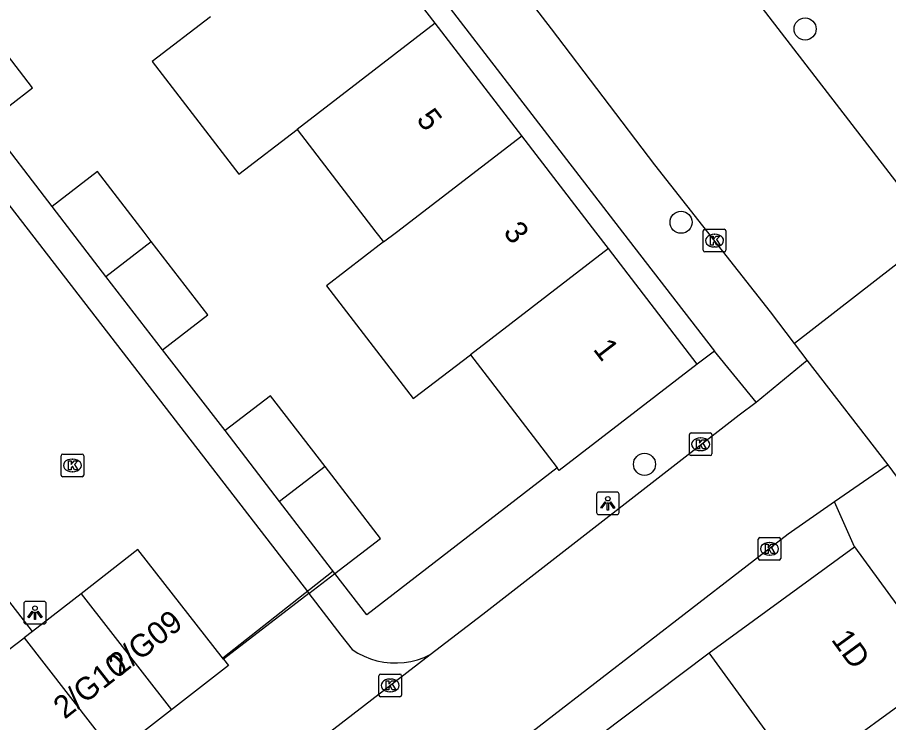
# Model space of a CAD drawing. Extents: x 159222 to 160346, y 381249 to 382166.
# Drawn here: x 159730.02 to 159768.58, y 381478.29 to 381509.5 of the extents above; entities that cross this region are included whole.
import ezdxf

# ---------------------------------------------------------------- set-up
doc = ezdxf.new("R2010")
doc.units = 0
for name, color, linetype in [('IMGEO_Boom', 7, 'Continuous'), ('IMGEO_Hek', 7, 'Continuous'), ('IMGEO_Kolk', 7, 'Continuous'), ('IMGEO_Lichtpunt', 7, 'Continuous'), ('IMGEO_Muur', 7, 'Continuous'), ('IMGEO_Pand', 7, 'Continuous'), ('IMGEO_Pand_nummerreeks', 7, 'Continuous'), ('IMGEO_Rijbaan_lokaal_gesloten', 7, 'Continuous'), ('IMGEO_Rijbaan_lokaal_open', 7, 'Continuous'), ('IMGEO_Voetpad_open', 7, 'Continuous')]:
    doc.layers.add(name, color=color, linetype=linetype)

msp = doc.modelspace()

# ---------------------------------------------------------------- linework, layer by layer
at = {"layer": 'IMGEO_Boom'}
for centre in [(159764.885, 381508.987), (159759.393, 381500.434), (159757.775, 381489.722)]:
    msp.add_circle(centre, 0.489, dxfattribs=at)
at = {"layer": 'IMGEO_Hek'}
msp.add_lwpolyline([(159744.002, 381484.991), (159739.107, 381481.143)], dxfattribs=at)
at = {"layer": 'IMGEO_Kolk'}
for p, q in [((159760.375, 381499.196), (159760.375, 381500.048)), ((159760.45, 381500.122), (159761.302, 381500.122)), ((159760.863, 381499.902), (159760.888, 381499.902)), ((159761.376, 381500.048), (159761.376, 381499.196)), ((159761.302, 381499.122), (159760.45, 381499.122)), ((159760.886, 381499.342), (159760.861, 381499.342)), ((159759.76, 381490.181), (159759.76, 381491.033)), ((159759.835, 381491.107), (159760.687, 381491.107)), ((159760.761, 381491.033), (159760.761, 381490.181)), ((159760.248, 381490.887), (159760.273, 381490.887)), ((159732.032, 381490.17), (159732.884, 381490.17)), ((159760.271, 381490.327), (159760.246, 381490.327)), ((159731.957, 381489.244), (159731.957, 381490.096)), ((159732.445, 381489.95), (159732.47, 381489.95)), ((159732.958, 381490.096), (159732.958, 381489.244)), ((159760.687, 381490.107), (159759.835, 381490.107)), ((159732.468, 381489.39), (159732.443, 381489.39)), ((159732.884, 381489.17), (159732.032, 381489.17)), ((159762.805, 381485.554), (159762.805, 381486.406)), ((159762.88, 381486.48), (159763.732, 381486.48)), ((159763.806, 381486.406), (159763.806, 381485.554)), ((159763.293, 381486.26), (159763.318, 381486.26)), ((159763.316, 381485.7), (159763.291, 381485.7)), ((159763.732, 381485.48), (159762.88, 381485.48)), ((159746.02, 381479.51), (159746.02, 381480.362)), ((159746.095, 381480.436), (159746.947, 381480.436)), ((159746.508, 381480.216), (159746.533, 381480.216)), ((159747.021, 381480.362), (159747.021, 381479.51)), ((159746.947, 381479.436), (159746.095, 381479.436)), ((159746.531, 381479.656), (159746.506, 381479.656))]:
    msp.add_line(p, q, dxfattribs=at)
for points in [[(159760.375, 381499.196), (159760.375, 381500.048)], [(159760.45, 381500.122), (159761.302, 381500.122)], [(159760.696, 381499.822), (159760.819, 381499.822), (159760.819, 381499.671), (159760.949, 381499.822), (159761.113, 381499.822), (159760.967, 381499.671), (159761.12, 381499.422), (159760.968, 381499.422), (159760.883, 381499.586), (159760.819, 381499.519), (159760.819, 381499.422), (159760.696, 381499.422), (159760.696, 381499.822)], [(159761.376, 381500.048), (159761.376, 381499.196)], [(159761.302, 381499.122), (159760.45, 381499.122)], [(159759.76, 381490.181), (159759.76, 381491.033)], [(159759.835, 381491.107), (159760.687, 381491.107)], [(159760.761, 381491.033), (159760.761, 381490.181)], [(159760.081, 381490.807), (159760.204, 381490.807), (159760.204, 381490.656), (159760.334, 381490.807), (159760.498, 381490.807), (159760.352, 381490.656), (159760.505, 381490.407), (159760.353, 381490.407), (159760.268, 381490.571), (159760.204, 381490.504), (159760.204, 381490.407), (159760.081, 381490.407), (159760.081, 381490.807)], [(159732.032, 381490.17), (159732.884, 381490.17)], [(159731.957, 381489.244), (159731.957, 381490.096)], [(159732.278, 381489.87), (159732.401, 381489.87), (159732.401, 381489.719), (159732.531, 381489.87), (159732.695, 381489.87), (159732.549, 381489.719), (159732.702, 381489.47), (159732.55, 381489.47), (159732.465, 381489.634), (159732.401, 381489.567), (159732.401, 381489.47), (159732.278, 381489.47), (159732.278, 381489.87)], [(159732.958, 381490.096), (159732.958, 381489.244)], [(159760.687, 381490.107), (159759.835, 381490.107)], [(159732.884, 381489.17), (159732.032, 381489.17)], [(159762.805, 381485.554), (159762.805, 381486.406)], [(159762.88, 381486.48), (159763.732, 381486.48)], [(159763.806, 381486.406), (159763.806, 381485.554)], [(159763.126, 381486.18), (159763.249, 381486.18), (159763.249, 381486.029), (159763.379, 381486.18), (159763.543, 381486.18), (159763.397, 381486.029), (159763.55, 381485.78), (159763.398, 381485.78), (159763.313, 381485.944), (159763.249, 381485.877), (159763.249, 381485.78), (159763.126, 381485.78), (159763.126, 381486.18)], [(159763.732, 381485.48), (159762.88, 381485.48)], [(159746.02, 381479.51), (159746.02, 381480.362)], [(159746.095, 381480.436), (159746.947, 381480.436)], [(159746.341, 381480.136), (159746.464, 381480.136), (159746.464, 381479.985), (159746.594, 381480.136), (159746.758, 381480.136), (159746.612, 381479.985), (159746.765, 381479.736), (159746.613, 381479.736), (159746.528, 381479.9), (159746.464, 381479.833), (159746.464, 381479.736), (159746.341, 381479.736), (159746.341, 381480.136)], [(159747.021, 381480.362), (159747.021, 381479.51)], [(159746.947, 381479.436), (159746.095, 381479.436)]]:
    msp.add_lwpolyline(points, dxfattribs=at)
for centre, start, end in [((159760.452, 381500.046), 91.552, 178.448), ((159760.452, 381500.046), 91.552, 178.448), ((159761.3, 381500.046), 1.552, 88.448), ((159761.3, 381500.046), 1.552, 88.448), ((159760.452, 381499.198), 181.552, 268.448), ((159760.452, 381499.198), 181.552, 268.448), ((159761.3, 381499.198), 271.552, 358.448), ((159761.3, 381499.198), 271.552, 358.448), ((159759.837, 381491.031), 91.552, 178.448), ((159759.837, 381491.031), 91.552, 178.448), ((159760.685, 381491.031), 1.552, 88.448), ((159760.685, 381491.031), 1.552, 88.448), ((159732.034, 381490.094), 91.552, 178.448), ((159732.034, 381490.094), 91.552, 178.448), ((159732.882, 381490.094), 1.552, 88.448), ((159732.882, 381490.094), 1.552, 88.448), ((159759.837, 381490.183), 181.552, 268.448), ((159759.837, 381490.183), 181.552, 268.448), ((159760.685, 381490.183), 271.552, 358.448), ((159760.685, 381490.183), 271.552, 358.448), ((159732.034, 381489.246), 181.552, 268.448), ((159732.034, 381489.246), 181.552, 268.448), ((159732.882, 381489.246), 271.552, 358.448), ((159732.882, 381489.246), 271.552, 358.448), ((159762.882, 381486.404), 91.552, 178.448), ((159762.882, 381486.404), 91.552, 178.448), ((159763.73, 381486.404), 1.552, 88.448), ((159763.73, 381486.404), 1.552, 88.448), ((159762.882, 381485.556), 181.552, 268.448), ((159762.882, 381485.556), 181.552, 268.448), ((159763.73, 381485.556), 271.552, 358.448), ((159763.73, 381485.556), 271.552, 358.448), ((159746.097, 381480.36), 91.552, 178.448), ((159746.097, 381480.36), 91.552, 178.448), ((159746.945, 381480.36), 1.552, 88.448), ((159746.945, 381480.36), 1.552, 88.448), ((159746.097, 381479.512), 181.552, 268.448), ((159746.097, 381479.512), 181.552, 268.448), ((159746.945, 381479.512), 271.552, 358.448), ((159746.945, 381479.512), 271.552, 358.448)]:
    msp.add_arc(centre, 0.0765, start, end, dxfattribs=at)
for centre, major_axis, ratio, start_param, end_param in [((159760.862, 381499.622), (-0.387, 0.002), 0.722429, 4.712389, 7.853982), ((159760.887, 381499.622), (-0.39, 0.002), 0.717154, 1.570796, 4.712389), ((159760.247, 381490.607), (-0.387, 0.002), 0.722429, 4.712389, 7.853982), ((159760.272, 381490.607), (-0.39, 0.002), 0.717154, 1.570796, 4.712389), ((159732.444, 381489.67), (-0.387, 0.002), 0.722429, 4.712389, 7.853982), ((159732.469, 381489.67), (-0.39, 0.002), 0.717154, 1.570796, 4.712389), ((159763.292, 381485.98), (-0.387, 0.002), 0.722429, 4.712389, 7.853982), ((159763.317, 381485.98), (-0.39, 0.002), 0.717154, 1.570796, 4.712389), ((159746.507, 381479.936), (-0.387, 0.002), 0.722429, 4.712389, 7.853982), ((159746.532, 381479.936), (-0.39, 0.002), 0.717154, 1.570796, 4.712389)]:
    msp.add_ellipse(centre, major_axis=major_axis, ratio=ratio, start_param=start_param, end_param=end_param, dxfattribs=at)
at = {"layer": 'IMGEO_Lichtpunt'}
for p, q in [((159755.653, 381488.399), (159755.653, 381487.592)), ((159755.653, 381488.399), (159755.653, 381487.592)), ((159756.555, 381488.494), (159755.747, 381488.494)), ((159756.555, 381488.494), (159755.747, 381488.494)), ((159756.649, 381487.592), (159756.649, 381488.399)), ((159756.649, 381487.592), (159756.649, 381488.399)), ((159755.747, 381487.498), (159756.555, 381487.498)), ((159755.747, 381487.498), (159756.555, 381487.498)), ((159731.204, 381483.653), (159730.396, 381483.653)), ((159731.204, 381483.653), (159730.396, 381483.653)), ((159730.302, 381483.558), (159730.302, 381482.751)), ((159730.302, 381483.558), (159730.302, 381482.751)), ((159731.298, 381482.751), (159731.298, 381483.558)), ((159731.298, 381482.751), (159731.298, 381483.558)), ((159730.396, 381482.657), (159731.204, 381482.657)), ((159730.396, 381482.657), (159731.204, 381482.657))]:
    msp.add_line(p, q, dxfattribs=at)
for points in [[(159756.027, 381488.063), (159756.066, 381488.035), (159755.878, 381487.773), (159755.84, 381487.8), (159756.027, 381488.063)], [(159756.129, 381488.015), (159756.176, 381488.015), (159756.176, 381487.693), (159756.129, 381487.693), (159756.129, 381488.015)], [(159756.239, 381488.035), (159756.277, 381488.062), (159756.464, 381487.8), (159756.425, 381487.772), (159756.239, 381488.035)], [(159730.676, 381483.222), (159730.715, 381483.194), (159730.527, 381482.932), (159730.489, 381482.959), (159730.676, 381483.222)], [(159730.888, 381483.194), (159730.926, 381483.221), (159731.113, 381482.959), (159731.074, 381482.931), (159730.888, 381483.194)], [(159730.778, 381483.174), (159730.825, 381483.174), (159730.825, 381482.852), (159730.778, 381482.852), (159730.778, 381483.174)]]:
    msp.add_lwpolyline(points, dxfattribs=at)
for centre in [(159756.152, 381488.197), (159730.801, 381483.356)]:
    msp.add_circle(centre, 0.0994, dxfattribs=at)
for centre, start, end in [((159755.747, 381488.399), 90, 180), ((159755.747, 381488.399), 90, 180), ((159756.555, 381488.399), 0, 90), ((159756.555, 381488.399), 0, 90), ((159755.747, 381487.592), 180, 270), ((159755.747, 381487.592), 180, 270), ((159756.555, 381487.592), 270, 0), ((159756.555, 381487.592), 270, 360), ((159730.396, 381483.558), 90, 180), ((159730.396, 381483.558), 90, 180), ((159731.204, 381483.558), 0, 90), ((159731.204, 381483.558), 0, 90), ((159730.396, 381482.751), 180, 270), ((159730.396, 381482.751), 180, 270), ((159731.204, 381482.751), 270, 0), ((159731.204, 381482.751), 270, 360)]:
    msp.add_arc(centre, 0.0946, start, end, dxfattribs=at)
at = {"layer": 'IMGEO_Muur'}
msp.add_lwpolyline([(159753.414, 381475.928), (159760.63, 381481.373)], dxfattribs=at)
at = {"layer": 'IMGEO_Pand'}
for points in [[(159748.509, 381509.241), (159744.679, 381514.222)], [(159728.702, 381504.843), (159730.692, 381506.375), (159728.265, 381509.527)], [(159738.565, 381509.52), (159735.992, 381507.541), (159739.823, 381502.561), (159742.397, 381504.541)], [(159748.509, 381509.241), (159742.397, 381504.541)], [(159752.34, 381504.259), (159748.509, 381509.241)], [(159742.397, 381504.541), (159745.892, 381500), (159746.23, 381499.561)], [(159746.23, 381499.561), (159746.801, 381500), (159752.34, 381504.259)], [(159756.177, 381499.27), (159755.615, 381500), (159752.34, 381504.259)], [(159735.948, 381499.582), (159735.627, 381500), (159733.566, 381502.68), (159731.558, 381501.133)], [(159733.938, 381498.036), (159732.429, 381500), (159731.558, 381501.133)], [(159733.938, 381498.036), (159735.948, 381499.582)], [(159736.436, 381494.787), (159738.447, 381496.332), (159735.948, 381499.582)], [(159746.23, 381499.561), (159743.704, 381497.617), (159747.543, 381492.629), (159750.069, 381494.573)], [(159756.177, 381499.27), (159750.069, 381494.573)], [(159760.111, 381494.153), (159756.177, 381499.27)], [(159736.436, 381494.787), (159733.938, 381498.036)], [(159750.069, 381494.573), (159750.959, 381493.417), (159753.916, 381489.567)], [(159760.111, 381494.153), (159754.005, 381489.451), (159753.916, 381489.567)], [(159743.635, 381489.625), (159741.23, 381492.756), (159739.222, 381491.214)], [(159741.628, 381488.082), (159739.222, 381491.214)], [(159743.635, 381489.625), (159741.628, 381488.082)], [(159744.077, 381484.893), (159746.085, 381486.436), (159743.635, 381489.625)], [(159744.077, 381484.893), (159741.628, 381488.082)], [(159739.14, 381481.1), (159735.356, 381485.955), (159732.837, 381483.992)], [(159760.63, 381481.373), (159767.07, 381486.073)], [(159767.07, 381486.073), (159771.094, 381480.559)], [(159730.695, 381482.323), (159728.774, 381484.792)], [(159732.837, 381483.992), (159730.695, 381482.323)], [(159732.837, 381483.992), (159736.844, 381478.851)], [(159730.695, 381482.323), (159730.314, 381482.035)], [(159727.764, 381480.113), (159730.314, 381482.035)], [(159730.314, 381482.035), (159734.325, 381476.888)], [(159764.65, 381475.863), (159760.63, 381481.373)], [(159739.14, 381481.1), (159739.363, 381480.814), (159736.844, 381478.851)], [(159764.65, 381475.863), (159771.094, 381480.559)], [(159736.844, 381478.851), (159734.325, 381476.888)]]:
    msp.add_lwpolyline(points, dxfattribs=at)
at = {"layer": 'IMGEO_Rijbaan_lokaal_gesloten'}
for points in [[(159764.419, 381495.062), (159763.358, 381496.462), (159758.238, 381502.981), (159753.664, 381509), (159740.852, 381525.618), (159730.632, 381538.903)], [(159761.639, 381511.66), (159770.073, 381500.702), (159770.613, 381500), (159770.669, 381499.927)], [(159770.669, 381499.927), (159764.419, 381495.062)]]:
    msp.add_lwpolyline(points, dxfattribs=at)
at = {"layer": 'IMGEO_Rijbaan_lokaal_open'}
for points in [[(159764.981, 381494.334), (159764.419, 381495.062)], [(159762.721, 381492.467), (159764.981, 381494.334)], [(159768.565, 381489.696), (159764.981, 381494.334)], [(159748.29, 381481.298), (159750.62, 381483.094), (159761.958, 381491.907), (159762.721, 381492.467)], [(159768.565, 381489.696), (159766.186, 381488.065)], [(159773.167, 381483.677), (159769.23, 381488.8), (159768.565, 381489.696)], [(159766.186, 381488.065), (159764.131, 381486.626), (159751.301, 381476.717), (159744.553, 381471.43), (159742.623, 381469.918), (159739.562, 381467.58), (159734.756, 381463.908), (159734.716, 381463.878), (159732.148, 381461.916), (159729.658, 381459.972), (159727.311, 381458.139), (159725.019, 381456.349), (159718.247, 381451.061), (159710.157, 381444.811), (159708.054, 381443.186), (159705.454, 381441.178), (159700.32, 381437.219), (159693.644, 381432.07), (159691.194, 381430.18), (159689.16, 381428.611), (159683.372, 381424.074), (159680.529, 381421.765)], [(159742.92, 381484.004), (159739.14, 381481.1)], [(159742.92, 381484.004), (159744.342, 381482.166), (159744.836, 381481.526), (159745.093, 381481.366), (159745.364, 381481.229), (159745.646, 381481.117), (159745.936, 381481.031), (159746.234, 381480.971), (159746.535, 381480.938), (159746.838, 381480.932), (159747.141, 381480.953), (159747.44, 381481.001), (159747.734, 381481.075), (159748.02, 381481.175), (159748.29, 381481.298)], [(159697.98, 381442.46), (159701.918, 381445.502), (159718.274, 381458.259), (159737.837, 381473.24), (159748.29, 381481.298)]]:
    msp.add_lwpolyline(points, dxfattribs=at)
at = {"layer": 'IMGEO_Voetpad_open'}
for points in [[(159729.233, 381534.307), (159729.955, 381534.85), (159756.805, 381500), (159760.87, 381494.724)], [(159715.326, 381502.074), (159723.871, 381508.651), (159742.854, 381484.089), (159742.92, 381484.004)], [(159731.558, 381501.133), (159728.702, 381504.843)], [(159739.222, 381491.214), (159736.436, 381494.787)], [(159760.87, 381494.724), (159760.111, 381494.153)], [(159762.721, 381492.467), (159760.87, 381494.724)], [(159753.916, 381489.567), (159745.49, 381483.053), (159744.077, 381484.893)], [(159767.07, 381486.073), (159766.186, 381488.065)], [(159742.92, 381484.004), (159744.077, 381484.893)], [(159753.414, 381475.928), (159760.63, 381481.373)]]:
    msp.add_lwpolyline(points, dxfattribs=at)

# ---------------------------------------------------------------- texts
at = {"layer": 'IMGEO_Pand_nummerreeks'}
for s, rotation, p in [('5', 307.5602, (159747.646, 381504.981)), ('3', 307.5629, (159751.492, 381499.984)), ('1', 307.559, (159755.469, 381494.808)), ('2/G09', 38.0272, (159734.546, 381480.315)), ('1D', 306.1205, (159766.011, 381481.959)), ('2/G10', 38.0251, (159732.115, 381478.414))]:
    msp.add_text(s, height=1, rotation=rotation, dxfattribs=at).set_placement(p)

doc.saveas('drawing.dxf')
